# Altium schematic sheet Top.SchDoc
size A3
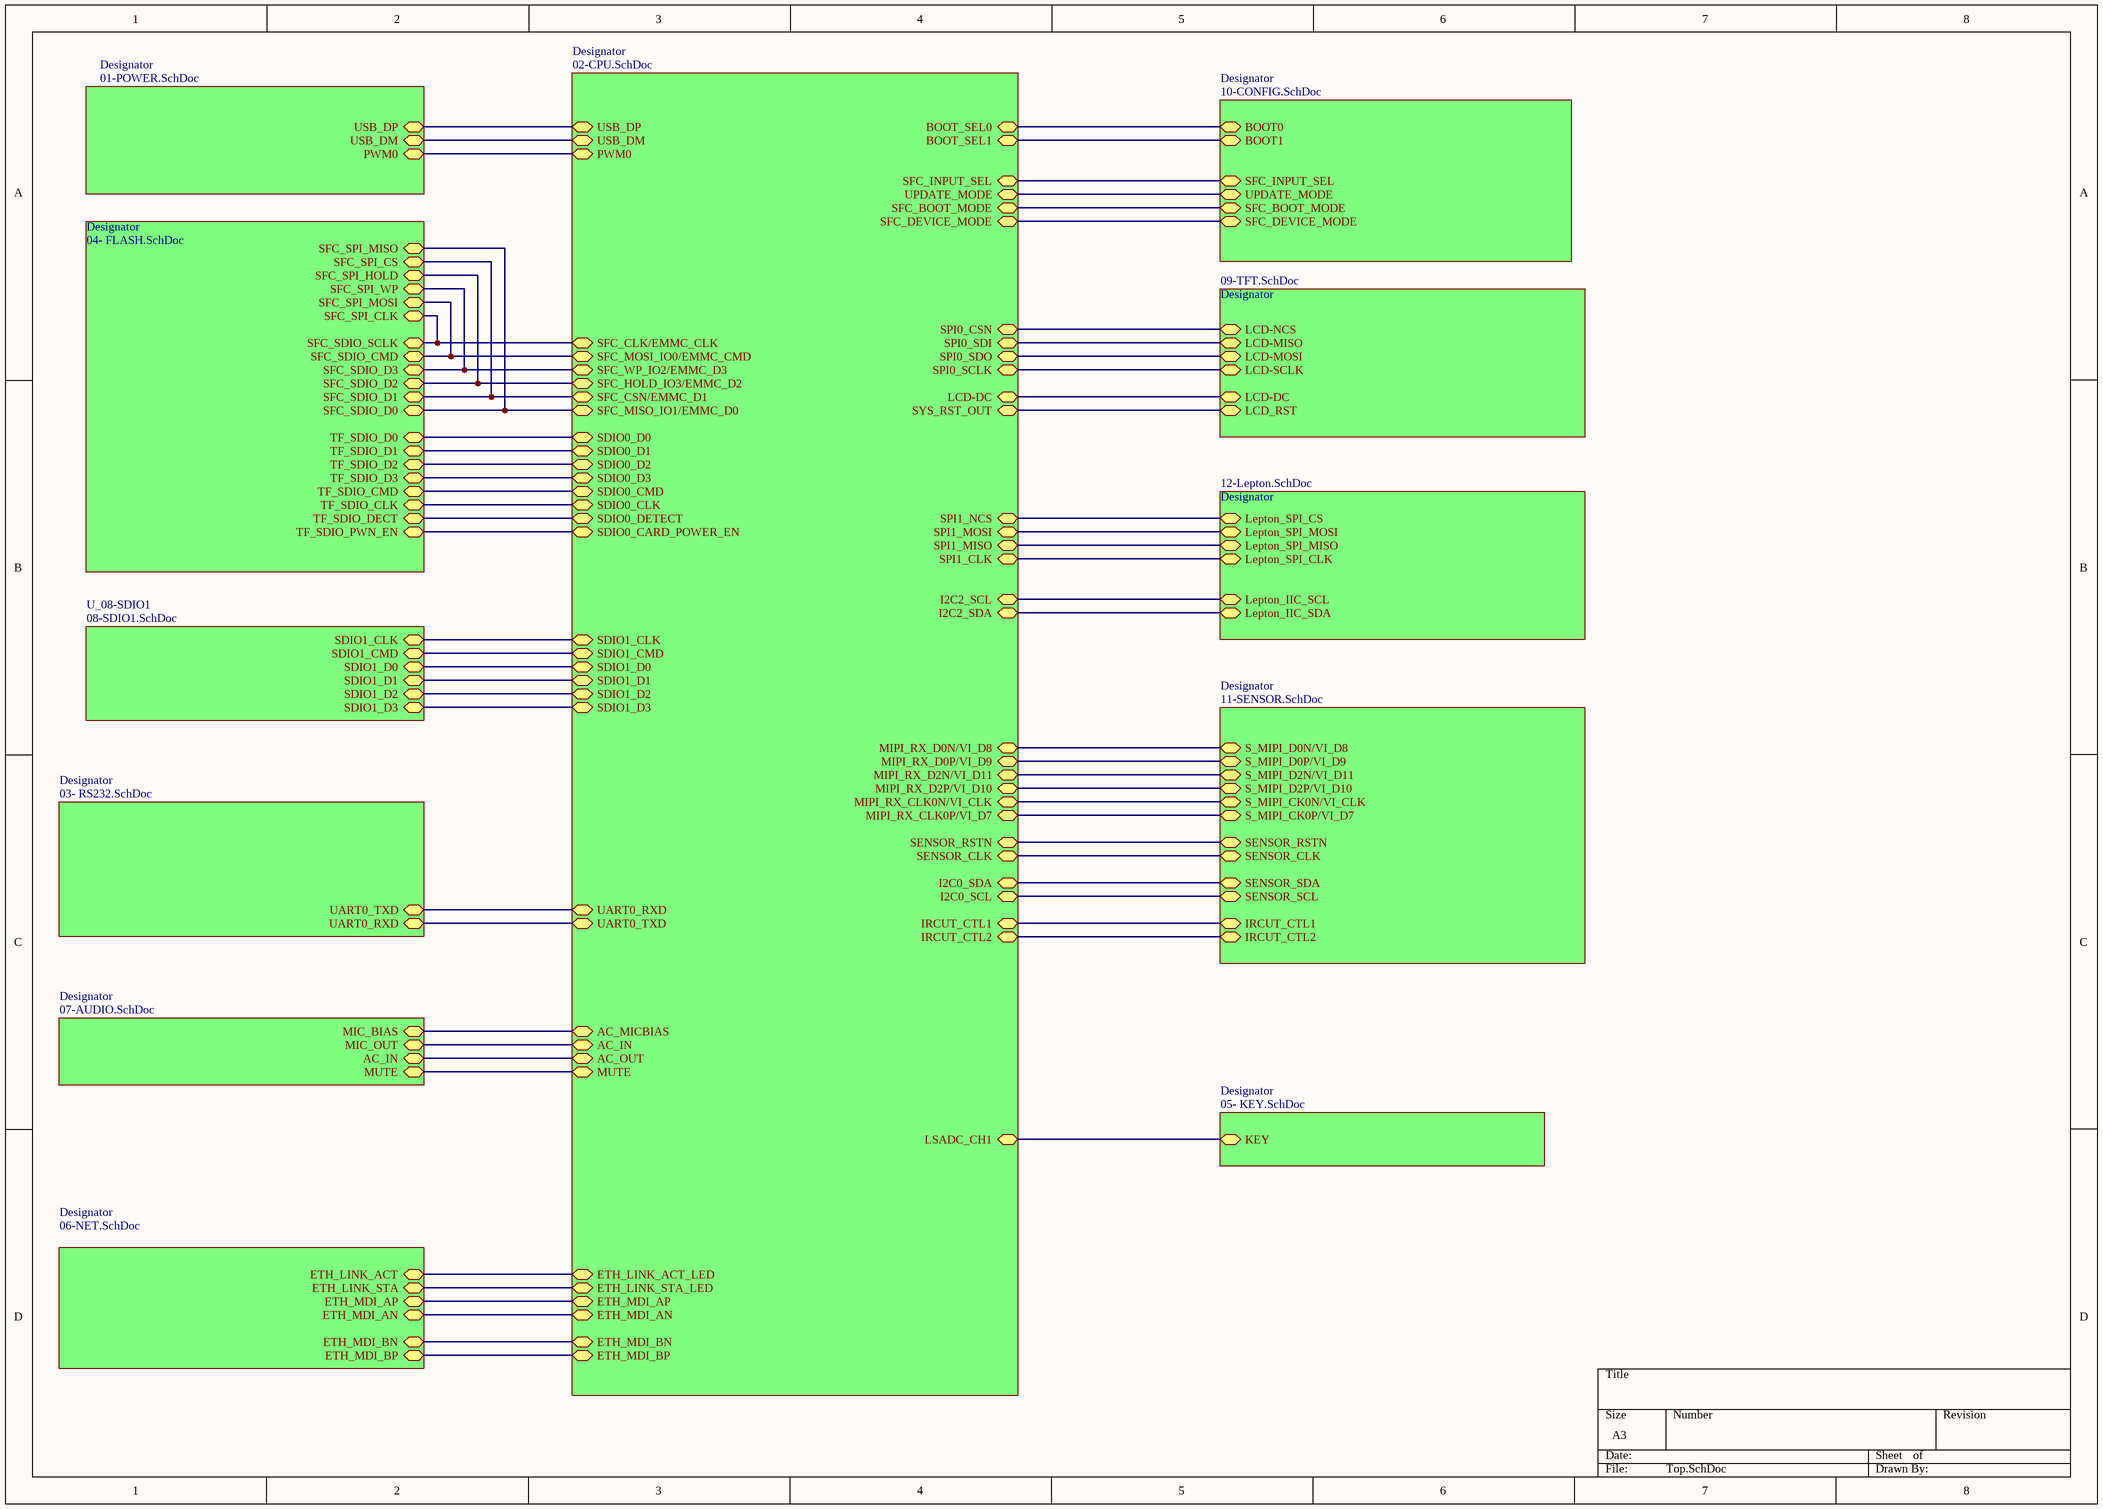
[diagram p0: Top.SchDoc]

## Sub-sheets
Designator = 02-CPU.SchDoc: ETH_LINK_STA_LED (bidir), ETH_MDI_BN (bidir), ETH_LINK_ACT_LED (bidir), ETH_MDI_AN (bidir), ETH_MDI_BP (bidir), ETH_MDI_AP (bidir), LSADC_CH1 (bidir), AC_IN (bidir), AC_OUT (bidir), AC_MICBIAS (bidir), MUTE (bidir), UART0_RXD (bidir), UART0_TXD (bidir), USB_DM (bidir), USB_DP (bidir), PWM0 (bidir), SFC_CSN/EMMC_D1 (bidir), SFC_MOSI_IO0/EMMC_CMD (bidir), SFC_MISO_IO1/EMMC_D0 (bidir), SFC_WP_IO2/EMMC_D3 (bidir), SFC_HOLD_IO3/EMMC_D2 (bidir), SFC_CLK/EMMC_CLK (bidir), SDIO0_D3 (bidir), SDIO0_D2 (bidir), SDIO0_D1 (bidir), SDIO1_CMD (bidir), SDIO1_D1 (bidir), SDIO1_D2 (bidir), SDIO1_CLK (bidir), SDIO1_D0 (bidir), SDIO0_D0 (bidir), SDIO0_CMD (bidir), SDIO0_DETECT (bidir), SDIO0_CLK (bidir), SDIO1_D3 (bidir), SDIO0_CARD_POWER_EN (bidir), MIPI_RX_D0N/VI_D8 (bidir), MIPI_RX_D2P/VI_D10 (bidir), MIPI_RX_D0P/VI_D9 (bidir), MIPI_RX_CLK0P/VI_D7 (bidir), MIPI_RX_CLK0N/VI_CLK (bidir), MIPI_RX_D2N/VI_D11 (bidir), I2C0_SCL (bidir), I2C0_SDA (bidir), SYS_RST_OUT (bidir), SENSOR_CLK (bidir), SPI0_CSN (bidir), SPI0_SDO (bidir), SPI0_SDI (bidir), SPI0_SCLK (bidir), SENSOR_RSTN (bidir), IRCUT_CTL2 (bidir), IRCUT_CTL1 (bidir), LCD-DC (bidir), BOOT_SEL1 (bidir), BOOT_SEL0 (bidir), SFC_INPUT_SEL (bidir), SFC_BOOT_MODE (bidir), SFC_DEVICE_MODE (bidir), UPDATE_MODE (bidir), SPI1_MOSI (bidir), I2C2_SCL (bidir), SPI1_NCS (bidir), SPI1_MISO (bidir), I2C2_SDA (bidir), SPI1_CLK (bidir)
Designator = 03- RS232.SchDoc: UART0_RXD (bidir), UART0_TXD (bidir)
Designator = 04- FLASH.SchDoc: TF_SDIO_CLK (bidir), TF_SDIO_D2 (bidir), TF_SDIO_D0 (bidir), TF_SDIO_D3 (bidir), TF_SDIO_D1 (bidir), TF_SDIO_DECT (bidir), TF_SDIO_CMD (bidir), TF_SDIO_PWN_EN (bidir), SFC_SPI_MISO (bidir), SFC_SPI_CS (bidir), SFC_SDIO_CMD (bidir), SFC_SDIO_SCLK (bidir), SFC_SDIO_D2 (bidir), SFC_SDIO_D3 (bidir), SFC_SDIO_D1 (bidir), SFC_SDIO_D0 (bidir), SFC_SPI_MOSI (bidir), SFC_SPI_CLK (bidir), SFC_SPI_HOLD (bidir), SFC_SPI_WP (bidir)
Designator = 06-NET.SchDoc: ETH_LINK_ACT (bidir), ETH_LINK_STA (bidir), ETH_MDI_AP (bidir), ETH_MDI_BN (bidir), ETH_MDI_AN (bidir), ETH_MDI_BP (bidir)
Designator = 09-TFT.SchDoc: LCD-DC (bidir), LCD-SCLK (bidir), LCD-NCS (bidir), LCD-MOSI (bidir), LCD_RST (bidir), LCD-MISO (bidir)
Designator = 11-SENSOR.SchDoc: SENSOR_CLK (bidir), SENSOR_SCL (bidir), IRCUT_CTL2 (bidir), S_MIPI_CK0N/VI_CLK (bidir), S_MIPI_CK0P/VI_D7 (bidir), SENSOR_SDA (bidir), SENSOR_RSTN (bidir), IRCUT_CTL1 (bidir), S_MIPI_D2N/VI_D11 (bidir), S_MIPI_D0P/VI_D9 (bidir), S_MIPI_D0N/VI_D8 (bidir), S_MIPI_D2P/VI_D10 (bidir)
Designator = 07-AUDIO.SchDoc: MIC_BIAS (bidir), MUTE (bidir), MIC_OUT (bidir), AC_IN (bidir)
Designator = 01-POWER.SchDoc: USB_DP (bidir), USB_DM (bidir), PWM0 (bidir)
Designator = 05- KEY.SchDoc: KEY (bidir)
Designator = 10-CONFIG.SchDoc: BOOT1 (bidir), SFC_INPUT_SEL (bidir), UPDATE_MODE (bidir), SFC_BOOT_MODE (bidir), BOOT0 (bidir), SFC_DEVICE_MODE (bidir)
Designator = 12-Lepton.SchDoc: Lepton_SPI_MOSI (bidir), Lepton_IIC_SDA (bidir), Lepton_SPI_CS (bidir), Lepton_SPI_CLK (bidir), Lepton_IIC_SCL (bidir), Lepton_SPI_MISO (bidir)
U_08-SDIO1 = 08-SDIO1.SchDoc: SDIO1_D2 (bidir), SDIO1_D3 (bidir), SDIO1_CMD (bidir), SDIO1_CLK (bidir), SDIO1_D0 (bidir), SDIO1_D1 (bidir)

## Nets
(unnamed): sheet Designator/ETH_LINK_STA_LED, sheet Designator/ETH_LINK_STA
(unnamed): sheet Designator/ETH_MDI_BN, sheet Designator/ETH_MDI_BN  [a separate net that carries the same name]
(unnamed): sheet Designator/ETH_LINK_ACT_LED, sheet Designator/ETH_LINK_ACT  [a separate net that carries the same name]
(unnamed): sheet Designator/ETH_MDI_AN, sheet Designator/ETH_MDI_AN  [a separate net that carries the same name]
(unnamed): sheet Designator/ETH_MDI_BP, sheet Designator/ETH_MDI_BP  [a separate net that carries the same name]
(unnamed): sheet Designator/ETH_MDI_AP, sheet Designator/ETH_MDI_AP  [a separate net that carries the same name]
(unnamed): sheet Designator/LSADC_CH1, sheet Designator/KEY  [a separate net that carries the same name]
(unnamed): sheet Designator/AC_IN, sheet Designator/MIC_OUT  [a separate net that carries the same name]
(unnamed): sheet Designator/AC_OUT, sheet Designator/AC_IN  [a separate net that carries the same name]
(unnamed): sheet Designator/AC_MICBIAS, sheet Designator/MIC_BIAS  [a separate net that carries the same name]
(unnamed): sheet Designator/MUTE, sheet Designator/MUTE  [a separate net that carries the same name]
(unnamed): sheet Designator/UART0_RXD, sheet Designator/UART0_TXD  [a separate net that carries the same name]
(unnamed): sheet Designator/UART0_TXD, sheet Designator/UART0_RXD  [a separate net that carries the same name]
(unnamed): sheet Designator/USB_DM, sheet Designator/USB_DM  [a separate net that carries the same name]
(unnamed): sheet Designator/USB_DP, sheet Designator/USB_DP  [a separate net that carries the same name]
(unnamed): sheet Designator/PWM0, sheet Designator/PWM0  [a separate net that carries the same name]
(unnamed): sheet Designator/SFC_CSN/EMMC_D1, sheet Designator/SFC_SPI_CS, sheet Designator/SFC_SDIO_D1  [a separate net that carries the same name]
(unnamed): sheet Designator/SFC_MOSI_IO0/EMMC_CMD, sheet Designator/SFC_SDIO_CMD, sheet Designator/SFC_SPI_MOSI  [a separate net that carries the same name]
(unnamed): sheet Designator/SFC_MISO_IO1/EMMC_D0, sheet Designator/SFC_SPI_MISO, sheet Designator/SFC_SDIO_D0  [a separate net that carries the same name]
(unnamed): sheet Designator/SFC_WP_IO2/EMMC_D3, sheet Designator/SFC_SDIO_D3, sheet Designator/SFC_SPI_WP  [a separate net that carries the same name]
(unnamed): sheet Designator/SFC_HOLD_IO3/EMMC_D2, sheet Designator/SFC_SDIO_D2, sheet Designator/SFC_SPI_HOLD  [a separate net that carries the same name]
(unnamed): sheet Designator/SFC_CLK/EMMC_CLK, sheet Designator/SFC_SDIO_SCLK, sheet Designator/SFC_SPI_CLK  [a separate net that carries the same name]
(unnamed): sheet Designator/SDIO0_D3, sheet Designator/TF_SDIO_D3  [a separate net that carries the same name]
(unnamed): sheet Designator/SDIO0_D2, sheet Designator/TF_SDIO_D2  [a separate net that carries the same name]
(unnamed): sheet Designator/SDIO0_D1, sheet Designator/TF_SDIO_D1  [a separate net that carries the same name]
(unnamed): sheet Designator/SDIO1_CMD, sheet U_08-SDIO1/SDIO1_CMD  [a separate net that carries the same name]
(unnamed): sheet Designator/SDIO1_D1, sheet U_08-SDIO1/SDIO1_D1  [a separate net that carries the same name]
(unnamed): sheet Designator/SDIO1_D2, sheet U_08-SDIO1/SDIO1_D2  [a separate net that carries the same name]
(unnamed): sheet Designator/SDIO1_CLK, sheet U_08-SDIO1/SDIO1_CLK  [a separate net that carries the same name]
(unnamed): sheet Designator/SDIO1_D0, sheet U_08-SDIO1/SDIO1_D0  [a separate net that carries the same name]
(unnamed): sheet Designator/SDIO0_D0, sheet Designator/TF_SDIO_D0  [a separate net that carries the same name]
(unnamed): sheet Designator/SDIO0_CMD, sheet Designator/TF_SDIO_CMD  [a separate net that carries the same name]
(unnamed): sheet Designator/SDIO0_DETECT, sheet Designator/TF_SDIO_DECT  [a separate net that carries the same name]
(unnamed): sheet Designator/SDIO0_CLK, sheet Designator/TF_SDIO_CLK  [a separate net that carries the same name]
(unnamed): sheet Designator/SDIO1_D3, sheet U_08-SDIO1/SDIO1_D3  [a separate net that carries the same name]
(unnamed): sheet Designator/SDIO0_CARD_POWER_EN, sheet Designator/TF_SDIO_PWN_EN  [a separate net that carries the same name]
(unnamed): sheet Designator/MIPI_RX_D0N/VI_D8, sheet Designator/S_MIPI_D0N/VI_D8  [a separate net that carries the same name]
(unnamed): sheet Designator/MIPI_RX_D2P/VI_D10, sheet Designator/S_MIPI_D2P/VI_D10  [a separate net that carries the same name]
(unnamed): sheet Designator/MIPI_RX_D0P/VI_D9, sheet Designator/S_MIPI_D0P/VI_D9  [a separate net that carries the same name]
(unnamed): sheet Designator/MIPI_RX_CLK0P/VI_D7, sheet Designator/S_MIPI_CK0P/VI_D7  [a separate net that carries the same name]
(unnamed): sheet Designator/MIPI_RX_CLK0N/VI_CLK, sheet Designator/S_MIPI_CK0N/VI_CLK  [a separate net that carries the same name]
(unnamed): sheet Designator/MIPI_RX_D2N/VI_D11, sheet Designator/S_MIPI_D2N/VI_D11  [a separate net that carries the same name]
(unnamed): sheet Designator/I2C0_SCL, sheet Designator/SENSOR_SCL  [a separate net that carries the same name]
(unnamed): sheet Designator/I2C0_SDA, sheet Designator/SENSOR_SDA  [a separate net that carries the same name]
(unnamed): sheet Designator/SYS_RST_OUT, sheet Designator/LCD_RST  [a separate net that carries the same name]
(unnamed): sheet Designator/SENSOR_CLK, sheet Designator/SENSOR_CLK  [a separate net that carries the same name]
(unnamed): sheet Designator/SPI0_CSN, sheet Designator/LCD-NCS  [a separate net that carries the same name]
(unnamed): sheet Designator/SPI0_SDO, sheet Designator/LCD-MOSI  [a separate net that carries the same name]
(unnamed): sheet Designator/SPI0_SDI, sheet Designator/LCD-MISO  [a separate net that carries the same name]
(unnamed): sheet Designator/SPI0_SCLK, sheet Designator/LCD-SCLK  [a separate net that carries the same name]
(unnamed): sheet Designator/SENSOR_RSTN, sheet Designator/SENSOR_RSTN  [a separate net that carries the same name]
(unnamed): sheet Designator/IRCUT_CTL2, sheet Designator/IRCUT_CTL2  [a separate net that carries the same name]
(unnamed): sheet Designator/IRCUT_CTL1, sheet Designator/IRCUT_CTL1  [a separate net that carries the same name]
(unnamed): sheet Designator/LCD-DC, sheet Designator/LCD-DC  [a separate net that carries the same name]
(unnamed): sheet Designator/BOOT_SEL1, sheet Designator/BOOT1  [a separate net that carries the same name]
(unnamed): sheet Designator/BOOT_SEL0, sheet Designator/BOOT0  [a separate net that carries the same name]
(unnamed): sheet Designator/SFC_INPUT_SEL, sheet Designator/SFC_INPUT_SEL  [a separate net that carries the same name]
(unnamed): sheet Designator/SFC_BOOT_MODE, sheet Designator/SFC_BOOT_MODE  [a separate net that carries the same name]
(unnamed): sheet Designator/SFC_DEVICE_MODE, sheet Designator/SFC_DEVICE_MODE  [a separate net that carries the same name]
(unnamed): sheet Designator/UPDATE_MODE, sheet Designator/UPDATE_MODE  [a separate net that carries the same name]
(unnamed): sheet Designator/SPI1_MOSI, sheet Designator/Lepton_SPI_MOSI  [a separate net that carries the same name]
(unnamed): sheet Designator/I2C2_SCL, sheet Designator/Lepton_IIC_SCL  [a separate net that carries the same name]
(unnamed): sheet Designator/SPI1_NCS, sheet Designator/Lepton_SPI_CS  [a separate net that carries the same name]
(unnamed): sheet Designator/SPI1_MISO, sheet Designator/Lepton_SPI_MISO  [a separate net that carries the same name]
(unnamed): sheet Designator/I2C2_SDA, sheet Designator/Lepton_IIC_SDA  [a separate net that carries the same name]
(unnamed): sheet Designator/SPI1_CLK, sheet Designator/Lepton_SPI_CLK  [a separate net that carries the same name]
